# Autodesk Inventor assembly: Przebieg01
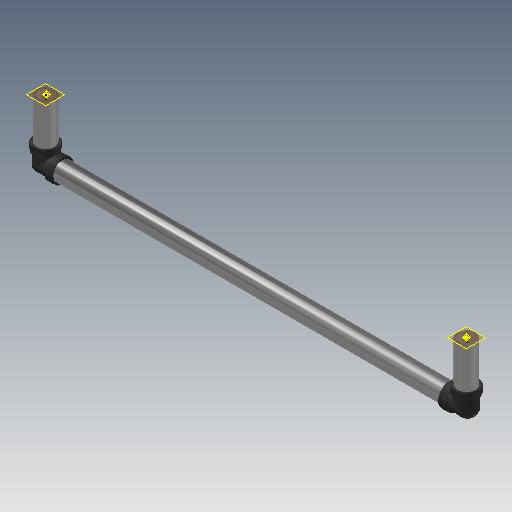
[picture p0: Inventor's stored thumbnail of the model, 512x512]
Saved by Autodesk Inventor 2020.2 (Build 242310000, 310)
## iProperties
Name: JIS G 3458/JIS B 2316 - Rury stalowe spawane i łączniki
ActiveState: True
PipeType: Rigid Pipe
Material: UnInitValue
Standard: UnInitValue
FittingMaterial: UnInitValue
FittingStandard: UnInitValue
RouteDirection90: True
RouteDirection45: True
IsFlanged: False
IsButtWelded: False
DiameterType: Nominal
Diameter: M40
Schedule: 80
OD: UnInitValue
ID: UnInitValue
Ending: UnInitValue
IntermediateSegmentsMin: 60,000 mm
IntermediateSegmentsMax: 5000,000 mm
IntermediateSegmentsInc: 1,000 mm
TerminationSegmentsMin: 60,000 mm
TerminationSegmentsMax: 5000,000 mm
TerminationSegmentsInc: 1,000 mm
RoundUpValue: UnInitValue
PipingComponentColor: As Material
PipeKey: v3#da14b0ab-0b36-4851-8d66-8c9cd0bcbe86#23
CouplingKey: v3#12b64993-10e6-4915-8315-0c0cce209ad0#8
Elbow90Key: v3#1f65ece3-c41a-48d4-8661-909ed34ade86#8
Elbow45Key: v3#28e76e79-e22c-40ab-8be2-ff545b1407c5#8
FlangeKey: UnInitValue
GasketKey: UnInitValue
Gap: UnInitValue
_ComponentInfo: <CS><C N="Pipe" R="2.430000" IR="1.920000" PL="PL" PN="JIS G 3458 Pipe 40 A x Sch 80"><CO N="1"><FE V="0"/><FD V="1"/><ET V="Welded"/><NS V="M40"/><MA V="0.0000
ShowGap: UnInitValue
MixedUnits: False
UseFlangsForCouplings: UnInitValue
IsSelfDraining: False
ElbowCustomKey: UnInitValue
Manager: www.cadconsulting.pl
Company: Fabian Stasiak CAD Consulting
Created: 2014-08
Part Number: Przebieg01
Document SubType Name: Assembly
Designer: F.Stasiak
Catalog Web Link: www.expertbooks.pl
Author: F.Stasiak
Subject: Zbiór ćwiczeń. Autodesk Inventor 2020. Kurs Professional
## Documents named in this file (6)
- C:\2020_Kurs_Professional\R1 Rury\Trasa sztywna_4\AIP\Przewody rurowe\Przebieg01\Trasa sztywna_4.Przebieg01.iam
- C:\2020_Kurs_Professional\R1 Rury\Trasa sztywna_4\AIP\Przewody rurowe\Przebieg01\Trasa sztywna_4.Trasa01.ipt
- C:\2020_Kurs_Professional\R1 Rury\Trasa sztywna_4\AIP\Przewody rurowe\Przebieg01\pipipe.1406895846444.ipt
- C:\2020_Kurs_Professional\R1 Rury\Trasa sztywna_4\AIP\Przewody rurowe\Przebieg01\pipipe.1406895847804.ipt
- C:\2020_Kurs_Professional\Zasoby\ContentCenter\pl-PL\JIS B 2316 90 (1)\JIS B 2316 Kolano 90 stopni 40A x Sch 80.ipt
- C:\2020_Kurs_Professional\R1 Rury\Trasa sztywna_4\AIP\Przewody rurowe\Przebieg01\pipipe.1426676357244.ipt
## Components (6 placed, 5 different names)
1. Trasa01
2. Segment rurowy 1:1
3. JIS B 2316 Kolano 90 stopni 40A x Sch 80:1
4. Segment rurowy 6:1
5. JIS B 2316 Kolano 90 stopni 40A x Sch 80:2
6. Segment rurowy 3:1
